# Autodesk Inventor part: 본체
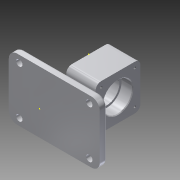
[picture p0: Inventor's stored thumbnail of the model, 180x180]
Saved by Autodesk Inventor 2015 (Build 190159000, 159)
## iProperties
Created: 2020-11
Part Number: 본체
Material: 알루미늄 6061
Document SubType Name: Modeling
Designer: pc-04
Density: 2.7 g/cm^3
Appearance: 알루미늄 - 평지
Mass: 645.497 g
Surface Area: 516.854 cm^2
Volume: 239.073 cm^3
Author: pc-04
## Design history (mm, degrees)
sketch "스케치2"
  geometry: L1 (-32, 32)-(32, 32); L2 (32, 32)-(32, -32); L3 (32, -32)-(-32, -32); L4 (-32, -32)-(-32, 32); L5 (0, 7.175)-(0, -7.867) reference; L6 (9.729, 0)-(-7.281, 0) reference; 1 further point
  constraints: 12 end point, 3 horizontal, 2 parallel, 2 vertical, 1 perpendicular, 3 other
  dimensions: "d0" = 64 distance of L1.end L2.end; "d1" = 64 distance of L2.end L3.end; "d2" = 32 distance between parallel lines of L3 L6; "d3" = 32 distance between parallel lines of L4 L5
extrude "돌출1" new body sketch "스케치2" distance "d4" = 42; taper "d5" = 0 deg
sketch "스케치5"
  geometry: 1 further point
sketch "스케치6"
  geometry: C1 r 21 at (0, 0); 1 further point
  constraints: 1 centre point, 1 coincident
  dimensions: "d17" = 42 diameter of C1
extrude "돌출3" cut sketch "스케치6" distance "d18" = 16; taper "d19" = 0 deg
sketch "스케치7"
  geometry: C1 r 21 at (0, 0); 1 further point
  constraints: 1 centre point, 1 coincident
  dimensions: "d20" = 42 diameter of C1
extrude "돌출4" cut sketch "스케치7" distance "d21" = 16; taper "d22" = 0 deg
sketch "스케치8"
  geometry: 1 further point
sketch "스케치9"
  geometry: C1 r 18 at (0, 0); 1 further point
  constraints: 1 centre point, 1 coincident
  dimensions: "d23" = 36 diameter of C1
extrude "돌출5" cut sketch "스케치9" distance "d24" = 16; taper "d25" = 0 deg
sketch "스케치10"
  geometry: 4 further points
hole "구멍1" sketch "스케치10" at (-24, 24), (-24, -24), (24, -24), (24, 24) diameter "d31" = 3.242; stored, may be unused: countersink angle "d35" = 90 deg, drill point angle "d37" = 118 deg; dims "d32" = 8, "d33" = 4, "d34" = 2, "d36" = 10
sketch "스케치11"
  geometry: L1 (0, 42.923)-(0, -48.07); L2 (-61.306, 0)-(57.445, 0); L3 (24, 42.923)-(24, -48.07); L4 (-24, 42.923)-(-24, -48.07); L5 (-61.306, 24)-(57.445, 24); L6 (-61.306, -24)-(57.445, -24); 5 further points
  constraints: 12 end point, 8 point on line, 4 parallel, 1 horizontal, 1 vertical
  dimensions: "d38" = 24 distance between parallel lines of L1 L3; "d39" = 24 distance between parallel lines of L1 L4; "d40" = 24 distance between parallel lines of L2 L5; "d41" = 24 distance between parallel lines of L2 L6
hole "구멍2" sketch "스케치11" at (-24, 24), (-24, -24), (24, -24), (24, 24) diameter "d42" = 3.242; stored, may be unused: countersink angle "d46" = 90 deg, drill point angle "d48" = 118 deg; dims "d43" = 8, "d44" = 4, "d45" = 2, "d47" = 10
node "작업 평면2"
sketch "스케치14"
  geometry: 1 further point
sketch "스케치15"
  geometry: 1 further point
sketch "스케치16" dims "d24" = 16
  geometry: L1 (-42, -32)-(0, -32); L2 (44, 52)-(-86, 52); L3 (-86, 52)-(-86, -36); L4 (-86, -36)-(44, -36); L5 (44, -36)-(44, 52); L6 (0, -33.785)-(0, 34.387); L7 (0, 32)-(0, -32) reference; L8 (-21, -33.785)-(-21, 34.387)
  constraints: 14 end point, 3 parallel, 1 collinear, 1 horizontal, 1 perpendicular, 1 other
  dimensions: "d78" = 130 distance of L2.start L2.end; "d79" = 88 distance of L2.end L3.end; "d201" = 21 distance between parallel lines of L6 L8; "d202" = 65 distance between parallel lines of L5 L8
extrude "돌출8" join sketch "스케치16" distance "d84" = 10; taper "d85" = 0 deg
sketch "스케치19"
  geometry: L1 (0, -32)-(42, -32); L2 (42, 32)-(0, 32); L3 (47.791, -32)-(-18.485, -32); L4 (86, 36)-(-44, 36) reference; L5 (0, 32)-(0, -4); L6 (0, -20)-(0, -32); L7 (4, -20)-(4, -39.483); L8 (4, -20)-(-18.485, -20); L9 (17, -32)-(17, -39.483); L10 (21, -32)-(21, -39.483); L11 (25, -32)-(25, -39.483); L12 (47.791, -20)-(38, -20); L13 (25, -20)-(17, -20); L14 (38, -20)-(38, -39.483); L15 (42, -20)-(42, -39.483); L16 (42, -32)-(42, -20); L17 (42, -4)-(42, 0); L18 (42, 4)-(42, 32); L19 (42, 36)-(42, 4); L20 (42, 0)-(42, -4); L21 (47.791, 4)-(42, 4); L22 (38, 36)-(38, 20); L23 (38, 4)-(38, -4); L24 (47.791, 20)-(38, 20); L25 (25, 36)-(25, 32); L26 (21, 36)-(21, 32); L27 (17, 36)-(17, 32); L28 (25, 20)-(17, 20); L29 (4, 20)-(-18.485, 20); L30 (4, 36)-(4, 20); L31 (4, 4)-(4, -4); L32 (0, 4)-(-18.485, 4); L33 (0, 0)-(-18.485, 0); L34 (0, -4)-(-18.485, -4); L35 (17, 20)-(17, 4); L36 (17, -4)-(17, -20); L37 (25, 20)-(25, 4); L38 (25, -4)-(25, -20); L39 (38, -4)-(25, -4); L40 (17, -4)-(4, -4); L41 (38, 4)-(25, 4); L42 (17, 4)-(4, 4)
  constraints: 82 end point, 55 parallel, 11 point on line, 3 perpendicular, 2 horizontal, 1 midpoint
extrude "돌출11" join sketch "스케치19" distance "d159" = 30; taper "d160" = 0 deg
fillet "모깎기1" dims "d172" = 8
sketch "스케치20"
  geometry: L1 (-39, -54.344)-(-39, 46.653); L2 (-41.097, -52)-(84.907, -52); L3 (-44, -52)-(86, -52) reference; L4 (-29, -54.344)-(-29, 46.653); L5 (71, -54.344)-(71, 46.653); L6 (-41.097, -42)-(84.907, -42); L7 (-41.097, 26)-(84.907, 26); 5 further points
  constraints: 12 end point, 8 point on line, 4 parallel, 1 collinear, 1 vertical
  dimensions: "d173" = 10 distance between parallel lines of L1 L4; "d174" = 110 distance between parallel lines of L1 L5; "d175" = 10 distance between parallel lines of L2 L6; "d176" = 78 distance between parallel lines of L2 L7
hole "구멍3" sketch "스케치20" at (71, -42), (71, 26), (-29, -42), (-29, 26) diameter "d177" = 9; stored, may be unused: countersink angle "d181" = 90 deg, drill point angle "d183" = 118 deg; dims "d178" = 8, "d179" = 4, "d180" = 2, "d182" = 10
fillet "모깎기2" dims "d184" = 12
fillet "모깎기3" dims "d185" = 12
chamfer "모따기1" distance "d186" = 1; stored, may be unused: second distance "d187" = 2, angle "d188" = 45 deg
fillet "모깎기4" dims "d189" = 0.3
chamfer "모따기2" distance "d190" = 1; stored, may be unused: second distance "d191" = 2, angle "d192" = 45 deg
fillet "모깎기5" dims "d193" = 3
fillet "모깎기6" dims "d194" = 3
fillet "모깎기7" dims "d195" = 3
fillet "모깎기8" dims "d196" = 3
sketch "스케치21"
  geometry: L1 (0, 32)-(42, 32); L2 (42, 32)-(42, -32); L3 (42, -32)-(0, -32); L4 (0, -32)-(0, 32); L5 (-7.399, 32)-(51.311, 32); L6 (-7.399, 0)-(51.311, 0); L7 (-32, -52)-(74, -52) reference; L8 (-44, 24)-(-44, -40) reference; 2 further points
  constraints: 12 end point, 3 parallel, 2 horizontal, 1 perpendicular, 1 point on line, 1 other
  dimensions: "d197" = 32 distance between parallel lines of L5 L6; "d200" = 65 distance from line of L8 point (21, -42)
feature "엠보싱1" sketch "스케치21" dims "d0" = 64, "d1" = 64, "d2" = 32, "d3" = 32, "d203" = 0.5, "d204" = 0
sketch "스케치22"
  geometry: 1 further point
node "솔리드1"
other parameters: "d64" = 62, "d65" = 65, "d66" = 4, "d67" = 4, "d68" = 4, "d69" = 4, "d74" = 17, "d75" = 17, "d87" = 44, "d88" = 4, "d89" = 4, "d90" = 4, "d91" = 4, "d92" = 17, "d93" = 17, "d101" = 65, "d102" = 52, "d104" = 4, "d105" = 4, "d106" = 4, "d107" = 4, "d108" = 17, "d109" = 17, "d112" = 55, "d113" = 62, "d114" = 4, "d115" = 4, "d116" = 4, "d117" = 4, "d118" = 4, "d119" = 17, "d120" = 17, "d125" = 65, "d126" = 4, "d127" = 4, "d128" = 4, "d129" = 4, "d130" = 17, "d131" = 17, "d148" = 62, "d151" = 4, "d152" = 4, "d153" = 4, "d154" = 4, "d155" = 17, "d156" = 17, "d162" = 32, "d163" = 21, "d164" = 4, "d165" = 4, "d166" = 4, "d167" = 4, "d168" = 17, "d169" = 17
